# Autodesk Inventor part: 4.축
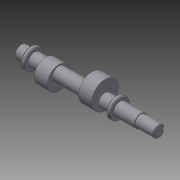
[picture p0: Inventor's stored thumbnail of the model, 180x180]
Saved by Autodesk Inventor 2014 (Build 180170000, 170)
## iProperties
Created: 2014-12
Part Number: 4.축
Material: 일반
Document SubType Name: Modeling
Designer: Owner
Density: 1 g/cm^3
Appearance: 기본값
Author: Owner
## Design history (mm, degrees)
sketch "스케치2"
  geometry: L1 (-90, 0)-(90, 0); L2 (-90, 0)-(-90, 7.5); L3 (-90, 7.5)-(-66, 7.5); L4 (-66, 7.5)-(-66, 8.5); L5 (-66, 8.5)-(-39, 8.5); L6 (-39, 8.5)-(-39, 13); L7 (-39, 13)-(-34, 13); L8 (-34, 13)-(-34, 8.5); L9 (-34, 8.5)-(72, 8.5); L10 (72, 8.5)-(72, 13); L11 (72, 13)-(77, 13); L12 (77, 13)-(77, 8.5); L13 (77, 8.5)-(90, 8.5); L14 (90, 8.5)-(90, 0); 2 further points
  constraints: 28 end point, 11 parallel, 2 coincident, 2 perpendicular, 1 horizontal, 1 midpoint
  dimensions: "d9" = 180 distance of L1.end L1.start; "d10" = 15 diameter of L3 L1; "d11" = 17 diameter of L5 L1; "d12" = 24 distance between parallel lines of L2 L4; "d13" = 27 distance between parallel lines of L4 L6; "d14" = 26 diameter of L7 L1; "d15" = 17 diameter of L9 L1; "d16" = 17 diameter of L13 L1; "d17" = 5 distance between parallel lines of L6 L8; "d18" = 26 diameter of L11 L1; "d19" = 5 distance between parallel lines of L10 L12; "d20" = 13 distance between parallel lines of L14 L12
revolve "회전1" sketch "스케치2" stored, may be unused: angle "d21" = 90 deg
node "작업 평면1"
sketch "스케치3"
  geometry: L1 (-90, -7.5)-(-90, 7.5) reference; L2 (-90, 2.5)-(-72.5, 2.5); L3 (-90, -2.5)-(-72.5, -2.5); A1 r 2.5 centre (-72.5, 0) between (-72.5, -2.5) and (-72.5, 2.5); 2 further points
  constraints: 4 end point, 2 point on circle, 2 point on line, 1 centre point, 1 horizontal alignment, 1 midpoint, 1 perpendicular, 1 tangent
  dimensions: "d23" = 5 diameter of A1; "d24" = 5 distance between parallel lines of L3 L2; "d25" = 17.5 distance from line of L1 A1.centre
extrude "돌출1" cut sketch "스케치3" distance "d26" = 3; taper "d27" = 0 deg
sketch "스케치4"
  geometry: L1 (-19.5, 6)-(-2.5, 6); L2 (-34, -8.5)-(72, -8.5) reference; L3 (-34, 8.5)-(72, 8.5) reference; L4 (-19.5, 6)-(-19.5, 23.5); L5 (-19.5, 23.5)-(-2.5, 23.5); L6 (-2.5, 23.5)-(-2.5, 6); L7 (-90, -7.5)-(-90, 7.5) reference; 3 further points
  constraints: 8 end point, 2 parallel, 2 perpendicular, 1 horizontal
  dimensions: "d28" = 6 distance from line of point (0, 0) L1; "d29" = 17 distance of L1.end L1.start; "d30" = 35 diameter of L5 L1; "d31" = 87.5 distance between parallel lines of L6 L7
revolve "회전2" sketch "스케치4" stored, may be unused: angle "d32" = 90 deg
sketch "스케치5"
  geometry: L1 (40.5, -5)-(57.5, -5); L2 (-2.5, 8.5)-(72, 8.5) reference; L3 (-2.5, -8.5)-(72, -8.5) reference; L4 (40.5, -5)-(40.5, 10); L5 (40.5, 10)-(57.5, 10); L6 (57.5, 10)-(57.5, -5); L7 (90, -8.5)-(90, 8.5) reference; 1 further point
  constraints: 8 end point, 3 perpendicular, 1 horizontal, 1 parallel
  dimensions: "d33" = 5 distance from line of point (0, 0) L1; "d34" = 17 distance of L1.end L1.start; "d35" = 49.5 distance between parallel lines of L7 L4; "d36" = 30 diameter of L5 L1
revolve "회전3" sketch "스케치5" stored, may be unused: angle "d37" = 90 deg
chamfer "모따기1" distance "d38" = 1; stored, may be unused: second distance "d39" = 2, angle "d40" = 45 deg
node "솔리드1"
other parameters: "d22" = 7.5
